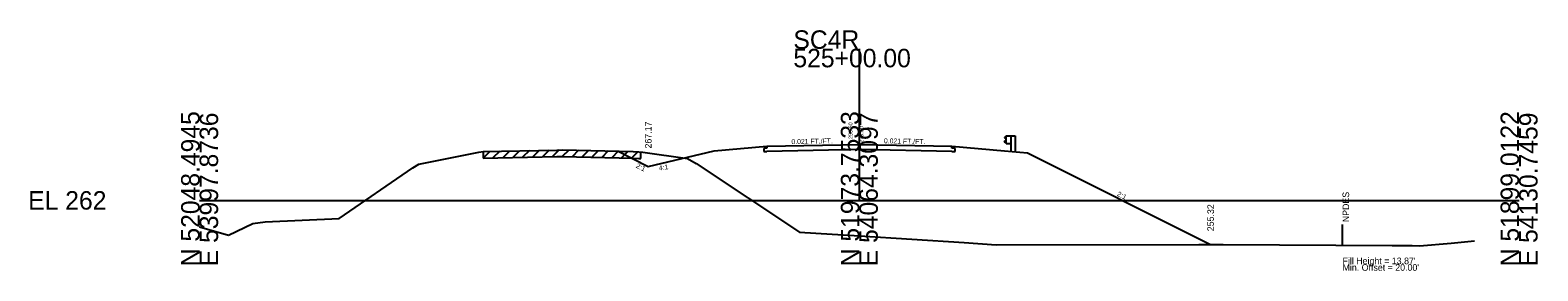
# Model space of a CAD drawing. Extents: x 7498 to 13027, y 90095 to 109625.
# Drawn here: x 9498.3 to 9726.8, y 95094.5 to 95131 of the extents above; entities that cross this region are included whole.
import ezdxf

# ---------------------------------------------------------------- set-up
doc = ezdxf.new("R2010")
doc.units = 0
for name, color, linetype in [('Level 10', 7, 'Continuous'), ('Level 11', 7, 'Continuous'), ('Level 12', 7, 'Continuous'), ('Level 24', 7, 'Continuous'), ('Level 32', 7, 'Continuous'), ('Level 33', 7, 'Continuous'), ('Level 50', 7, 'Continuous'), ('Level 55', 7, 'Continuous'), ('Level 59', 7, 'Continuous'), ('Level 6', 7, 'Continuous'), ('Level 60', 7, 'Continuous'), ('Level 61', 7, 'Continuous'), ('Level 63', 7, 'Continuous'), ('Level 7', 7, 'Continuous')]:
    doc.layers.add(name, color=color, linetype=linetype)

msp = doc.modelspace()

# ---------------------------------------------------------------- linework, layer by layer
at = {"layer": 'Level 11'}
for p, q in [((9609.99, 95113.07), (9609.49, 95113.05)), ((9609.49, 95113.05), (9609.49, 95112.57)), ((9609.49, 95112.57), (9609.99, 95112.59)), ((9609.99, 95113.37), (9609.99, 95113.07)), ((9637.99, 95113.07), (9637.99, 95113.37)), ((9638.49, 95113.05), (9637.99, 95113.07)), ((9637.99, 95112.59), (9638.49, 95112.57)), ((9638.49, 95112.57), (9638.49, 95113.05))]:
    msp.add_line(p, q, dxfattribs=at)
at = {"layer": 'Level 12'}
for p, q in [((9623.99, 95112.88), (9609.99, 95112.59)), ((9637.99, 95112.59), (9623.99, 95112.88))]:
    msp.add_line(p, q, dxfattribs=at)
at = {"layer": 'Level 24'}
for p, q in [((9646.26, 95114.88), (9645.99, 95114.68)), ((9646.26, 95113.78), (9646.26, 95114.95)), ((9646.26, 95114.95), (9646.93, 95114.95)), ((9646.93, 95114.95), (9646.93, 95112.6)), ((9646.93, 95114.95), (9647.6, 95114.95)), ((9647.6, 95114.95), (9647.6, 95112.54)), ((9645.99, 95114.68), (9645.99, 95114.63)), ((9645.99, 95114.63), (9646.26, 95114.43)), ((9645.99, 95114.1), (9646.26, 95114.3)), ((9645.99, 95114.05), (9645.99, 95114.1)), ((9646.26, 95113.85), (9645.99, 95114.05)), ((9646.26, 95113.78), (9646.93, 95113.78))]:
    msp.add_line(p, q, dxfattribs=at)
at = {"layer": 'Level 55'}
msp.add_line((9697.23, 95098.48), (9697.23, 95101.48), dxfattribs=at)
at = {"layer": 'Level 59'}
for p, q in [((9609.99, 95113.37), (9623.99, 95113.66)), ((9623.99, 95113.66), (9637.99, 95113.37))]:
    msp.add_line(p, q, dxfattribs=at)
at = {"layer": 'Level 6'}
for p, q in [((9601.99, 95112.7), (9609.99, 95113.37)), ((9637.99, 95113.37), (9645.99, 95112.7)), ((9645.99, 95112.7), (9649.49, 95112.35))]:
    msp.add_line(p, q, dxfattribs=at)
at = {"layer": 'Level 60'}
for p, q in [((9566.33, 95112.47), (9566.95, 95112.55)), ((9566.95, 95112.55), (9578.15, 95112.8)), ((9578.15, 95112.8), (9578.99, 95112.82)), ((9578.99, 95112.82), (9589.73, 95112.55)), ((9589.73, 95112.55), (9590.57, 95112.53)), ((9590.57, 95112.53), (9591.16, 95112.45)), ((9556.31, 95110.11), (9557.22, 95110.67)), ((9557.22, 95110.67), (9566.33, 95112.47)), ((9591.16, 95112.45), (9597.95, 95111.51)), ((9597.95, 95111.51), (9599.25, 95110.76)), ((9599.25, 95110.76), (9614.92, 95100.34)), ((9545.15, 95102.39), (9556.31, 95110.11)), ((9523.99, 95101.15), (9528.36, 95099.9)), ((9528.36, 95099.9), (9532.08, 95101.66)), ((9532.08, 95101.66), (9533.93, 95101.88)), ((9533.93, 95101.88), (9545.15, 95102.39)), ((9614.92, 95100.34), (9623.99, 95099.76)), ((9623.99, 95099.76), (9639.86, 95098.75)), ((9713.71, 95098.65), (9717.22, 95099.03)), ((9639.86, 95098.75), (9644.72, 95098.39)), ((9644.72, 95098.39), (9675.45, 95098.47)), ((9675.45, 95098.47), (9679.14, 95098.49)), ((9679.14, 95098.49), (9704.75, 95098.32)), ((9704.75, 95098.32), (9707.77, 95098.32)), ((9707.77, 95098.32), (9708.87, 95098.28)), ((9708.87, 95098.28), (9713.71, 95098.65))]:
    msp.add_line(p, q, dxfattribs=at)
at = {"layer": 'Level 61'}
for p, q in [((9567.97, 95112.58), (9566.95, 95111.55)), ((9566.95, 95112.55), (9566.95, 95111.55)), ((9569.47, 95112.61), (9568.45, 95111.59)), ((9570.97, 95112.64), (9569.95, 95111.62)), ((9572.47, 95112.68), (9571.45, 95111.65)), ((9573.97, 95112.71), (9572.95, 95111.69)), ((9575.47, 95112.74), (9574.45, 95111.72)), ((9576.97, 95112.78), (9575.95, 95111.75)), ((9578.47, 95112.81), (9577.45, 95111.79)), ((9579.93, 95112.8), (9578.95, 95111.82)), ((9581.42, 95112.76), (9580.45, 95111.78)), ((9582.92, 95112.72), (9581.95, 95111.75)), ((9584.42, 95112.68), (9583.45, 95111.71)), ((9585.92, 95112.65), (9584.95, 95111.67)), ((9587.42, 95112.61), (9586.45, 95111.63)), ((9588.92, 95112.57), (9587.95, 95111.59)), ((9590.43, 95112.53), (9589.45, 95111.56)), ((9566.95, 95111.55), (9578.15, 95111.8)), ((9578.15, 95111.8), (9578.99, 95111.82)), ((9578.99, 95111.82), (9589.73, 95111.55)), ((9589.73, 95111.55), (9590.57, 95111.53)), ((9590.57, 95111.53), (9590.87, 95111.49)), ((9590.87, 95111.49), (9590.87, 95112.49))]:
    msp.add_line(p, q, dxfattribs=at)
at = {"layer": 'Level 63'}
for p, q in [((9623.99, 95105.16), (9623.99, 95128.15)), ((9523.99, 95105.16), (9623.99, 95105.16)), ((9623.99, 95105.16), (9723.99, 95105.16))]:
    msp.add_line(p, q, dxfattribs=at)
at = {"layer": 'Level 7'}
for p, q in [((9587.42, 95112.61), (9591.99, 95110.32)), ((9591.99, 95110.32), (9601.99, 95112.7)), ((9649.49, 95112.35), (9677.23, 95098.48))]:
    msp.add_line(p, q, dxfattribs=at)

# ---------------------------------------------------------------- texts
at = {"layer": 'Level 10'}
msp.add_text('256.60', height=0.6, rotation=90, dxfattribs=at).set_placement((9622.95, 95114.46))
at = {"layer": 'Level 32'}
for s, rotation, p in [('0.021 FT./FT.', 1.1916, (9613.7, 95113.69)), ('0.021 FT./FT.', 358.8084, (9627.71, 95113.83)), ('2:1', 333.435, (9590.06, 95110.17)), ('4:1', 9.4623, (9593.66, 95109.67)), ('2:1', 333.435, (9662.97, 95105.89))]:
    msp.add_text(s, height=0.75, rotation=rotation, dxfattribs=at).set_placement(p)
at = {"layer": 'Level 33'}
for s, p in [('267.17', (9592.49, 95113.03)), ('255.32', (9677.73, 95100.48))]:
    msp.add_text(s, height=1, rotation=90, dxfattribs=at).set_placement(p)
at = {"layer": 'Level 50'}
msp.add_text(' NPDES', height=1, rotation=90, dxfattribs=at).set_placement((9698.23, 95101.48))
for s, p in [("Fill Height = 13.87' ", (9697.23, 95095.48)), ("Min. Offset = 20.00' ", (9697.23, 95094.48))]:
    msp.add_text(s, height=1, dxfattribs=at).set_placement(p)
at = {"layer": 'Level 59'}
msp.add_text(' 270.50', height=0.6, rotation=90, dxfattribs=at).set_placement((9624.59, 95113.66))
at = {"layer": 'Level 63'}
for s, p in [('SC4R', (9613.99, 95128.15)), ('525+00.00', (9613.99, 95125.35)), ('EL 262', (9498, 95103.76))]:
    msp.add_text(s, height=2.8, dxfattribs=at).set_placement(p)
for s, p in [('N 52048.4945', (9523.99, 95095.16)), ('E 53997.8736', (9526.79, 95095.16)), ('N 51973.7533', (9623.99, 95095.16)), ('E 54064.3097', (9626.79, 95095.16)), ('N 51899.0122', (9723.99, 95095.16)), ('E 54130.7459', (9726.79, 95095.16))]:
    msp.add_text(s, height=2.8, rotation=90, dxfattribs=at).set_placement(p)

doc.saveas('drawing.dxf')
